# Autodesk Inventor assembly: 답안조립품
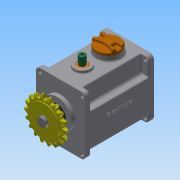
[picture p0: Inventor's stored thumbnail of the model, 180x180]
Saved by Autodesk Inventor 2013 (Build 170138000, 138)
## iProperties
Created: 2016-09
Part Number: 답안조립품
Document SubType Name: Assembly
Designer: Administrator
Author: Administrator
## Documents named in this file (17)
- C:\Users\Administrator\Desktop\360908V1003\답안조립품.iam
- C:\Users\Administrator\Desktop\360908V1003\360908V1003\본체.ipt
- C:\Users\Administrator\Desktop\360908V1003\360908V1003\부시.ipt
- C:\Users\Administrator\Desktop\360908V1003\360908V1003\오일실 17 32 8.ipt
- C:\Users\Administrator\Desktop\360908V1003\360908V1003\베어링 6003.ipt
- C:\Users\Administrator\Desktop\360908V1003\360908V1003\서브축.ipt
- C:\Users\Administrator\Desktop\360908V1003\360908V1003\슬라이더.ipt
- C:\Users\Administrator\Desktop\360908V1003\가변스프링.ipt
- C:\Users\Administrator\Desktop\360908V1003\360908V1003\오일실 8 22 7.ipt
- C:\Users\Administrator\Desktop\360908V1003\360908V1003\상부 캡.ipt
- C:\Users\Administrator\Desktop\360908V1003\360908V1003\커버.ipt
- C:\Users\Administrator\Desktop\360908V1003\360908V1003\베어링 608.ipt
- C:\Users\Administrator\Desktop\360908V1003\360908V1003\메인축.ipt
- C:\Users\Administrator\Desktop\360908V1003\360908V1003\볼트 M4 x 10.ipt
- C:\Users\Administrator\Desktop\360908V1003\360908V1003\멈춤나사 M3x8.ipt
- C:\Users\Administrator\Desktop\360908V1003\360908V1003\스프로킷.ipt
- C:\Users\Administrator\Desktop\360908V1003\360908V1003\키 5 x 5 x 18.ipt
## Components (3 placed, 2 different names)
1. 가변스프링:1
2. ISO 4762 M4 x 10:1
3. ISO 4762 M4 x 10:2
